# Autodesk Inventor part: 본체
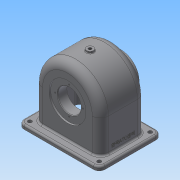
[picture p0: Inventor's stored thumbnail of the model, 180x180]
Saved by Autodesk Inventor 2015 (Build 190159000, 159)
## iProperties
Created: 2022-09
Part Number: 본체
Material: 일반
Document SubType Name: Modeling
Designer: 학생용
Density: 1 g/cm^3
Appearance: 기본값
Author: 학생용
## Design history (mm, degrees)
sketch "스케치1"
  geometry: L1 (0, 0)-(0, 64); L2 (57, 64)-(57, 0); L3 (57, 0)-(-57, 0); L4 (-57, 0)-(-57, 64); A1 r 57 centre (0, 64) between (57, 64) and (-57, 64)
  constraints: 8 end point, 2 point on circle, 2 vertical, 1 centre point, 1 coincident, 1 perpendicular, 1 tangent
  dimensions: "d0" = 64 distance of L1.start L1.end; "d1" = 114 diameter of A1; "d2" = 114 distance of L2.end L3.end; "d3" = 64 distance of L2.start L2.end; "d4" = 64 distance of L4.end L3.end
extrude "돌출1" new body sketch "스케치1" stored distance "d5" = 78; taper "d6" = 0 deg
feature "쉘1" dims "d7" = 5
sketch "스케치2"
  geometry: L1 (-70, -54)-(70, -54); L2 (70, -54)-(70, 54); L3 (70, 54)-(-70, 54); L4 (-70, 54)-(-70, -54); L5 (-70, -54)-(70, 54); L6 (70, -54)-(-70, 54); L7 (-52, -34)-(52, -34) reference; L8 (52, -34)-(52, 34) reference; L9 (52, 34)-(-52, 34) reference; L10 (-52, 34)-(-52, -34) reference; L11 (57, -39)-(-57, -39) reference; L12 (-57, -39)-(-57, 39) reference; L13 (-57, 39)-(57, 39) reference; L14 (57, 39)-(57, -39) reference; 1 further point
  constraints: 12 end point, 2 midpoint, 2 parallel, 1 horizontal, 1 perpendicular
  dimensions: "d8" = 140 distance of L3.end L2.end; "d9" = 108 distance of L2.end L1.end
extrude "돌출2" join sketch "스케치2" distance "d10" = 7; taper "d11" = 0 deg
sketch "스케치4"
  geometry: L1 (-57, 7)-(57, 7) reference; L2 (57, 7)-(57, 64) reference; L3 (-57, 64)-(-57, 7) reference; C1 r 32 at (0, 64); A1 r 57 centre (0, 64) between (57, 64) and (-57, 64) reference; 1 further point
  constraints: 1 centre point, 1 coincident
  dimensions: "d12" = 64 diameter of C1
extrude "돌출3" cut sketch "스케치4" distance "d13" = 3; taper "d14" = 0 deg
sketch "스케치6"
  geometry: C1 r 32 at (0, 0) reference; C2 r 20 at (0, 0); 1 further point
  constraints: 1 centre point, 1 coincident
  dimensions: "d15" = 40 diameter of C2
extrude "돌출4" cut sketch "스케치6" stored distance "d16" = 3; taper "d17" = 0 deg
sketch "스케치7"
  geometry: L1 (54, 7)-(54, 0) reference; L2 (54, 0)-(34, 0) reference; L3 (34, 0)-(34, 116) reference; L4 (34, 116)-(-34, 116) reference; L5 (-34, 116)-(-34, 84) reference; L6 (-34, 84)-(-36, 84) reference; L7 (-36, 84)-(-36, 96) reference; L8 (-36, 96)-(-39, 96) reference; L9 (-39, 96)-(-39, 121) reference; L10 (-39, 121)-(39, 121) reference; L11 (39, 121)-(39, 7) reference; L12 (39, 7)-(54, 7) reference; L13 (-54, 0)-(-54, 7) reference; L14 (-54, 7)-(-39, 7) reference; L15 (-39, 7)-(-39, 32) reference; L16 (-39, 32)-(-36, 32) reference; L17 (-36, 32)-(-36, 44) reference; L18 (-36, 44)-(-34, 44) reference; L19 (-34, 44)-(-34, 0) reference; L20 (-34, 0)-(-54, 0) reference; L21 (39, 64)-(-39, 64); L22 (39, 64)-(-39, 64) reference; L23 (-20, 84)-(-20, 92); L24 (-20, 92)-(-34, 100.083); L25 (-34, 84)-(-20, 84); L26 (-39, 32)-(-39, 96) reference; L27 (-34, 100.083)-(-34, 84); L28 (-34, 84)-(-34, 44) reference; 1 further point
  constraints: 10 end point, 2 collinear, 2 perpendicular, 1 midpoint, 1 point on line
  dimensions: "d18" = 19 distance between parallel lines of L23 L26; "d19" = 120 deg angle of L23 L24; "d20" = 56 diameter of L23.end L21
revolve "회전1" sketch "스케치7" stored, may be unused: angle "d21" = 90 deg
sketch "스케치8"
  geometry: L1 (57, -7)-(-57, -7) reference; L2 (-57, -7)-(-57, -64) reference; L3 (57, -64)-(57, -7) reference; C1 r 31 at (0, -64); A1 r 57 centre (0, -64) between (-57, -64) and (57, -64) reference; 1 further point
  constraints: 1 centre point, 1 coincident
  dimensions: "d22" = 62 diameter of C1
extrude "돌출5" join sketch "스케치8" distance "d23" = 15; taper "d24" = 0 deg
sketch "스케치9"
  geometry: C1 r 20 at (0, 0) reference; C2 r 20 at (0, 0); 1 further point
  constraints: 1 centre point, 1 coincident
  dimensions: "d25" = 40 diameter of C2
extrude "돌출6" cut sketch "스케치9" distance "d26" = 16; taper "d27" = 0 deg
sketch "스케치10"
  geometry: C1 r 20 at (0, 0) reference; C2 r 17.5 at (0, 0); 1 further point
  constraints: 1 centre point, 1 coincident
  dimensions: "d28" = 35 diameter of C2
extrude "돌출7" cut sketch "스케치10" distance "d29" = 5; taper "d30" = 0 deg
fillet "모깎기1" dims "d31" = 10
sketch "스케치11"
  geometry: L1 (-60, -54)-(60, -54) reference; L2 (70, -44)-(70, 44) reference; L3 (60, 54)-(-60, 54) reference; L4 (-70, 44)-(-70, -44) reference; L5 (-57, 39)-(-57, -39) reference; L6 (57, 39)-(-57, 39) reference; L7 (57, -39)-(57, 39) reference; L8 (-57, -39)-(57, -39) reference; C1 r 3.3 at (-60, -44); C2 r 3.3 at (-60, 44); C3 r 3.3 at (60, 44); C4 r 3.3 at (60, -44); A1 r 10 centre (-60, -44) between (-70, -44) and (-60, -54) reference; A2 r 10 centre (60, -44) between (60, -54) and (70, -44) reference; A3 r 10 centre (60, 44) between (70, 44) and (60, 54) reference; A4 r 10 centre (-60, 44) between (-60, 54) and (-70, 44) reference; 1 further point
  constraints: 4 centre point, 4 coincident
  dimensions: "d32" = 6.6 diameter of C1; "d33" = 6.6 diameter of C2; "d34" = 6.6 diameter of C3; "d35" = 6.6 diameter of C4
extrude "돌출8" cut sketch "스케치11" stored distance "d36" = 0; taper "d37" = 0 deg
fillet "모깎기2" dims "d38" = 3
fillet "모깎기3" dims "d39" = 14
fillet "모깎기4" dims "d40" = 9
chamfer "모따기1" distance "d41" = 1; stored, may be unused: second distance "d42" = 2, angle "d43" = 45 deg
fillet "모깎기5" dims "d44" = 0.6
fillet "모깎기6" dims "d45" = 3
node "작업 평면1"
sketch "스케치12"
  geometry: C1 r 6 at (0, 0); 1 further point
  constraints: 1 centre point, 1 coincident
  dimensions: "d47" = 12 diameter of C1
extrude "돌출9" join sketch "스케치12" stored distance "d48" = 5; taper "d49" = 0 deg
fillet "모깎기7" dims "d50" = 1
sketch "스케치13"
  geometry: 2 further points
  constraints: 1 coincident
hole "구멍1" sketch "스케치13" at (0, 0) diameter "d51" = 5.188; stored, may be unused: countersink angle "d55" = 90 deg, drill point angle "d57" = 118 deg; dims "d52" = 12, "d53" = 4, "d54" = 2, "d56" = 16
sketch "스케치14" dims "d58" = 48
  geometry: L1 (0, 0)-(0, 24); C1 r 31 at (0, 0) reference; C2 r 26.268 at (0, 0) reference; 2 further points
  constraints: 2 coincident, 2 end point, 1 vertical, 1 vertical alignment, 2 other
hole "구멍2" sketch "스케치14" at (0, 24) diameter "d59" = 2.459; stored, may be unused: countersink angle "d63" = 90 deg, drill point angle "d65" = 118 deg; dims "d60" = 7, "d61" = 4, "d62" = 2, "d64" = 9
fillet "모깎기8" dims "d69" = 3
sketch "스케치15"
  geometry: L1 (0, 0)-(0, -24); C1 r 31 at (0, 0) reference; C2 r 21 at (0, 0) reference; C3 r 24 at (0, 0); C4 r 1.23 at (0, -24) reference; 2 further points
  constraints: 2 coincident, 2 end point, 1 centre point, 1 vertical
  dimensions: "d70" = 48 diameter of C3
hole "구멍3" sketch "스케치15" at (0, -24) diameter "d71" = 2.459; stored, may be unused: countersink angle "d75" = 90 deg, drill point angle "d77" = 118 deg; dims "d72" = 7, "d73" = 4, "d74" = 2, "d76" = 9
sketch "스케치16"
  geometry: L1 (64, -19)-(64, 69) reference; L2 (0, -14)-(57, -14) reference; 2 further points
  constraints: 1 other
  dimensions: "d81" = 17 distance from line of point (47, 25) L1; "d82" = 39 distance from line of point (47, 25) L2
fillet "모깎기9" dims "d83" = 3
feature "엠보싱1" dims "d0" = 64, "d1" = 114, "d2" = 114, "d3" = 64, "d4" = 64, "d84" = 0.5, "d85" = 0
node "솔리드1"
pattern_circular "원형 패턴1" dims angle "d67" = 360 deg
pattern_circular "원형 패턴2" dims angle "d79" = 360 deg
node "투영된 루프1"
node "투영된 루프2"
node "투영된 루프3"
node "투영된 루프4"
node "투영된 루프5"
node "투영된 루프6"
node "절단 모서리 투영1"
node "절단 모서리 투영4"
other parameters: "d46" = 124
